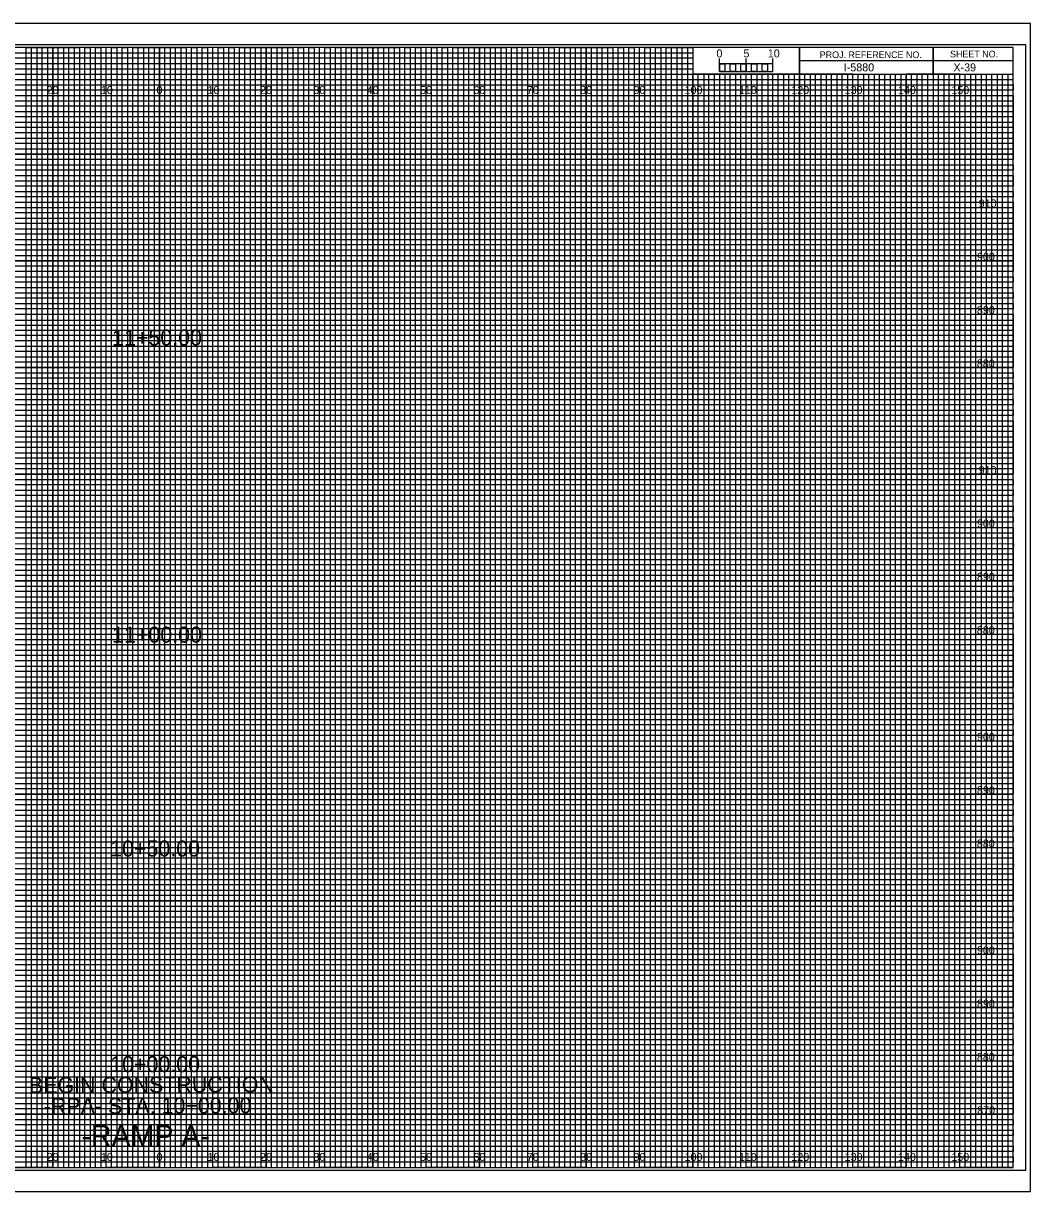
# Model space of a CAD drawing. Extents: x -13 to 323, y -4 to 214.
# Drawn here: x 134.5 to 323.3, y -4.5 to 214.5 of the extents above; entities that cross this region are included whole.
import ezdxf

# ---------------------------------------------------------------- set-up
doc = ezdxf.new("R2010")
doc.units = 0
for name, color, linetype in [('Prop XS Alignment Label', 7, 'Continuous'), ('Prop XS Bar Scale Labels', 7, 'Continuous'), ('Prop XS Elevation Labels', 7, 'Continuous'), ('Prop XS Offset Labels', 7, 'Continuous'), ('Prop XS Project Number', 7, 'Continuous'), ('Prop XS SE Text', 7, 'Continuous'), ('Prop XS Sheet Number', 7, 'Continuous'), ('Prop XS Station Labels', 7, 'Continuous'), ('Sheet Cross Section CELL', 7, 'Continuous'), ('Sheet Cross Section Grid Major CELL', 7, 'Continuous'), ('Sheet Cross Section Grid Middle CELL', 7, 'Continuous'), ('Sheet Cross Section Grid Minor 1 CELL', 7, 'Continuous'), ('Sheet Cross Section Grid Minor 2 CELL', 7, 'Continuous'), ('Sheet Cross Section Scale CELL', 7, 'Continuous'), ('Sheet Cutting Line CELL', 7, 'Continuous'), ('Sheet DOT Grid CELL', 7, 'Continuous'), ('Sheet Plot Border Inside CELL', 7, 'Continuous'), ('Sheet Plot Border Outside CELL', 7, 'Continuous')]:
    doc.layers.add(name, color=color, linetype=linetype)

msp = doc.modelspace()

# ---------------------------------------------------------------- linework, layer by layer
at = {"layer": 'Sheet Cross Section CELL'}
for p, q in [((305, 210), (305, 205)), ((305, 205), (305, 210)), ((280, 207.5), (280, 205)), ((320, 207.49), (280, 207.49)), ((280, 205), (320, 205))]:
    msp.add_line(p, q, dxfattribs=at)
for points in [[(320, 210), (0, 210), (0, 0), (320, 0)], [(280, 210), (260, 210), (260, 205.03), (280, 205.03)], [(320, 210), (280, 210), (280, 205), (320, 205)]]:
    msp.add_lwpolyline(points, close=True, dxfattribs=at)
at = {"layer": 'Sheet Cross Section Grid Major CELL'}
for p, q in [((150, 210), (140, 210)), ((140, 210), (140, 0)), ((150, 0), (150, 210)), ((170, 210), (160, 210)), ((160, 210), (160, 0)), ((170, 0), (170, 210)), ((190, 210), (180, 210)), ((180, 210), (180, 0)), ((190, 0), (190, 210)), ((210, 210), (200, 210)), ((200, 210), (200, 0)), ((210, 0), (210, 210)), ((230, 210), (220, 210)), ((220, 210), (220, 0)), ((230, 0), (230, 210)), ((250, 210), (240, 210)), ((240, 210), (240, 0)), ((250, 0), (250, 210)), ((260, 210), (260, 0)), ((270, 0), (270, 205)), ((290, 205), (280, 205)), ((280, 205), (280, 0)), ((290, 0), (290, 205)), ((310, 205), (300, 205)), ((300, 205), (300, 0)), ((310, 0), (310, 205)), ((140, 0), (130, 0)), ((160, 0), (150, 0)), ((180, 0), (170, 0)), ((200, 0), (190, 0)), ((220, 0), (210, 0)), ((240, 0), (230, 0)), ((260, 0), (250, 0)), ((280, 0), (270, 0)), ((300, 0), (290, 0)), ((320, 0), (310, 0)), ((320, 0), (320, 0))]:
    msp.add_line(p, q, dxfattribs=at)
for points in [[(0, 200), (320, 200), (320, 190), (0, 190)], [(0, 180), (320, 180), (320, 170), (0, 170)], [(0, 160), (320, 160), (320, 150), (0, 150)], [(0, 140), (320, 140), (320, 130), (0, 130)], [(0, 120), (320, 120), (320, 110), (0, 110)], [(0, 100), (320, 100), (320, 90), (0, 90)], [(0, 80), (320, 80), (320, 70), (0, 70)], [(0, 60), (320, 60), (320, 50), (0, 50)], [(0, 40), (320, 40), (320, 30), (0, 30)], [(0, 20), (320, 20), (320, 10), (0, 10)]]:
    msp.add_lwpolyline(points, dxfattribs=at)
at = {"layer": 'Sheet Cross Section Grid Middle CELL'}
for points in [[(125, 0), (135, 0), (135, 210), (145, 210), (145, 0), (155, 0), (155, 210), (165, 210), (165, 0), (175, 0), (175, 210), (185, 210), (185, 0), (195, 0), (195, 210), (205, 210), (205, 0), (215, 0), (215, 210), (225, 210), (225, 0), (235, 0), (235, 210), (245, 210), (245, 0), (255, 0), (255, 210), (259.93, 210), (260, 210), (260, 205), (264.99, 205), (264.99, 0), (275, 0), (275, 205), (285, 205), (285, 0), (295, 0), (295, 205), (305, 205), (305, 0), (315, 0), (315, 205)], [(0, 205), (275, 205)], [(0, 185), (320, 185), (320, 195), (0, 195)], [(0, 165), (320, 165), (320, 175), (0, 175)], [(0, 145), (320, 145), (320, 155), (0, 155)], [(0, 125), (320, 125), (320, 135), (0, 135)], [(0, 105), (320, 105), (320, 115), (0, 115)], [(0, 85), (320, 85), (320, 95), (0, 95)], [(0, 65), (320, 65), (320, 75), (0, 75)], [(0, 45), (320, 45), (320, 55), (0, 55)], [(0, 25), (320, 25), (320, 35), (0, 35)], [(0, 5), (320, 5), (320, 15), (0, 15)]]:
    msp.add_lwpolyline(points, dxfattribs=at)
at = {"layer": 'Sheet Cross Section Grid Minor 1 CELL'}
for p, q in [((0, 209), (260, 209)), ((260, 209), (260, 207.98)), ((260, 207.98), (0, 207.98)), ((0, 207), (260, 207)), ((260, 205.89), (0, 205.89)), ((260, 207), (260, 205.89)), ((0, 204), (320, 204))]:
    msp.add_line(p, q, dxfattribs=at)
for points in [[(0, 203), (270, 203), (320, 203), (320, 202), (0, 202)], [(0, 201), (320, 201), (320, 199), (0, 199)], [(0, 198), (320, 198), (320, 197), (0, 196.98)], [(0, 196), (320, 196), (320, 194), (0, 194)], [(0, 193), (320, 193), (320, 192), (0, 192)], [(0, 191), (320, 191), (320, 189), (0, 189)], [(0, 188), (320, 188), (320, 187), (0, 187)], [(0, 186), (320, 186), (320, 184), (0, 184)], [(0, 183), (320, 183), (320, 182), (0, 182)], [(0, 181), (320, 181), (320, 179), (0, 179)], [(0, 178), (320, 178), (320, 177), (0, 177)], [(0, 176), (320, 176), (320, 173.95), (320, 173), (320, 172), (0, 172)], [(0, 174), (320, 174), (320, 173), (0, 173)], [(0, 171), (320, 171), (320, 169), (0, 169.03)], [(0, 169.03), (320, 169), (320, 168), (0, 168)], [(0, 167), (320, 167), (320, 166), (0, 166)], [(0, 164), (320, 164), (320, 163), (0, 163)], [(0, 162), (320, 162), (320, 161), (0, 161)], [(-0.07, 158.89), (320, 158.89), (320, 157.88), (-0.07, 157.88)], [(0, 157), (320, 157), (320, 156), (0, 156)], [(0, 154), (320, 154), (320, 153), (0, 153)], [(0, 152), (320, 152), (320, 151), (0, 151)], [(0, 149), (320, 149), (320, 148), (0, 148)], [(0, 147), (320, 147), (320, 146), (0, 146)], [(0, 144), (320, 144), (320, 143), (0, 143)], [(0, 142), (320, 142), (320, 141), (0, 141)], [(0, 139), (320, 139), (319.99, 137.98), (0, 138)], [(0, 137), (320, 137), (320, 136), (0, 136)], [(0, 134), (320, 134), (320, 133), (0, 133)], [(0, 132), (320, 132), (320, 131), (0, 131)], [(0, 129), (320, 129), (320, 128), (0, 128)], [(0, 127), (320, 127), (320, 126), (0, 126)], [(0, 124), (320, 124), (320, 123), (0, 123)], [(0, 122), (320, 122), (320, 121), (0, 121)], [(0, 119), (320, 119), (320, 118), (0, 118)], [(0, 116.99), (320.07, 116.91), (320, 116), (0, 116)], [(0, 114), (320, 114), (320, 113), (0, 113)], [(0, 112), (320, 112), (320, 111), (0, 111)], [(0, 109), (320, 109), (320, 108), (0, 108)], [(0, 107), (320, 107), (320, 106), (0, 106)], [(0, 104), (320, 104), (320, 103), (0, 103)], [(0, 102), (320, 102), (320, 101), (0, 101)], [(0, 99), (320, 99), (320, 98), (0, 98)], [(0, 97), (320, 97), (320, 96), (0, 96)], [(0, 94), (320, 94), (320, 93), (0, 93)], [(0, 92), (320, 92), (320, 91), (0, 91)], [(0, 89), (320, 89), (320, 88), (0, 88)], [(0, 87), (320, 87), (320, 86), (0, 86)], [(0, 84), (320, 84), (320, 83), (0, 83)], [(0, 82), (320, 82), (320, 81), (0, 81)], [(0, 79), (320, 79), (319.99, 77.98), (0, 78)], [(0, 77), (320, 77), (320, 76), (0, 76)], [(0, 74), (320, 74), (320, 73), (0, 73)], [(0, 72), (320, 72), (320, 71), (0, 71)], [(0, 69), (320, 69), (320, 68), (0, 68)], [(0, 67), (320, 67), (320, 66), (0, 66)], [(0, 64), (320, 64), (320, 63), (0, 63)], [(0, 62), (320, 62), (320, 61), (0, 61)], [(0, 59), (320, 59), (320, 58), (0, 58)], [(0, 56.99), (320.07, 56.91), (320, 56), (0, 56)], [(0, 54), (320, 54), (320, 53), (0, 53)], [(0, 52), (320, 52), (320, 51), (0, 51)], [(0, 49), (320, 49), (320, 48), (0, 48)], [(0, 47), (320, 47), (320, 46), (0, 46)], [(0, 44), (320, 44), (320, 43), (0, 43)], [(0, 42), (320, 42), (320, 41), (0, 41)], [(0, 39), (320, 39), (320, 38), (0, 38)], [(0, 37), (320, 37), (320, 36), (0, 36)], [(0, 34), (320, 34), (320, 33), (0, 33)], [(0, 32), (320, 32), (320, 31), (0, 31)], [(0, 29), (320, 29), (320, 28), (0, 28)], [(0, 27), (320, 27), (320, 26), (0, 26)], [(0, 24), (320, 24), (320, 23), (0, 23)], [(0, 22), (320, 22), (320, 21), (0, 21)], [(0, 19), (320, 19), (320, 18), (0, 18)], [(0, 17), (320, 17), (320, 16), (0, 16)], [(0, 14), (320, 14), (320, 13), (0, 13)], [(0, 12), (320, 12), (320, 11), (0, 11)], [(0, 9), (320, 9), (320, 8), (0, 8)], [(0, 7), (320, 7), (320, 6), (0, 6)], [(0, 4), (320, 4), (320, 3), (0, 3)], [(0, 2), (320, 2), (320, 1), (0, 1)]]:
    msp.add_lwpolyline(points, dxfattribs=at)
at = {"layer": 'Sheet Cross Section Grid Minor 2 CELL'}
for p, q in [((267, 205), (266.01, 205)), ((266.01, 205), (266.01, 0)), ((267, 0), (267, 205)), ((269, 205), (268, 205)), ((268, 205), (268, 0)), ((269, 0), (269, 205)), ((266.01, 0), (265, 0)), ((268, 0), (267, 0))]:
    msp.add_line(p, q, dxfattribs=at)
for points in [[(135, 0), (136, 0), (136, 210), (137, 210), (137, 0)], [(137, 0), (138, 0), (138, 210), (139, 210), (139, 0)], [(140, 0), (141, 0), (141, 210), (142, 210), (142, 0)], [(142, 0), (143, 0), (143, 210), (144, 210), (144, 0)], [(145, 0), (146, 0), (146, 210), (147, 210), (147, 0)], [(147, 0), (148, 0), (148, 210), (149, 210), (149, 0)], [(150, 0), (151, 0), (151, 210), (152, 210), (152, 0)], [(152, 0), (153, 0), (153, 210), (154, 210), (154, 0)], [(155, 0), (156, 0), (156, 210), (157, 210), (157, 0)], [(157, 0), (158, 0), (158, 210), (159, 210), (159, 0)], [(160, 0), (161, 0), (161, 210), (162, 210), (162, 0)], [(162, 0), (163, 0), (163, 210), (164, 210), (164, 0)], [(165, 0), (166, 0), (166, 210), (167, 210), (167, 0)], [(167, 0), (168, 0), (168, 210), (169, 210), (169, 0)], [(170, 0), (171, 0), (171, 210), (172, 210), (172, 0)], [(172, 0), (173, 0), (173, 210), (174, 210), (174, 0)], [(175, 0), (176, 0), (176, 210), (177, 210), (177, 0)], [(177, 0), (178, 0), (178, 210), (179, 210), (179, 0)], [(180, 0), (181, 0), (181, 210), (182, 210), (182, 0)], [(182, 0), (183, 0), (183, 210), (184, 210), (184, 0)], [(185, 0), (186, 0), (186, 210), (187, 210), (187, 0)], [(187, 0), (188, 0), (188, 210), (189, 210), (189, 0)], [(190, 0), (191, 0), (191, 210), (192, 210), (192, 0)], [(192, 0), (193, 0), (193, 210), (194, 210), (194, 0)], [(195, 0), (196, 0), (196, 210), (197, 210), (197, 0)], [(197, 0), (198, 0), (198, 210), (199, 210), (199, 0)], [(200, 0), (201, 0), (201, 210), (202, 210), (202, 0)], [(202, 0), (203, 0), (203, 210), (204, 210), (204, 0)], [(205, 0), (206, 0), (206, 210), (207, 210), (207, 0)], [(207, 0), (208, 0), (208, 210), (209, 210), (209, 0)], [(210, 0), (211, 0), (211, 210), (212, 210), (212, 0)], [(212, 0), (213, 0), (213, 210), (214, 210), (214, 0)], [(215, 0), (216, 0), (216, 210), (217, 210), (217, 0)], [(217, 0), (218, 0), (218, 210), (219, 210), (219, 0)], [(220, 0), (221, 0), (221, 210), (222, 210), (222, 0)], [(222, 0), (223, 0), (223, 210), (224, 210), (224, 0)], [(225, 0), (226, 0), (226, 210), (227, 210), (227, 0)], [(227, 0), (228, 0), (228, 210), (229, 210), (229, 0)], [(230, 0), (231, 0), (231, 210), (232, 210), (232, 0)], [(232, 0), (233, 0), (233, 210), (234, 210), (234, 0)], [(235, 0), (236, 0), (236, 210), (237, 210), (237, 0)], [(237, 0), (238, 0), (238, 210), (239, 210), (239, 0)], [(240, 0), (241, 0), (241, 210), (242, 210), (242, 0)], [(242, 0), (243, 0), (243, 210), (244, 210), (244, 0)], [(245, 0), (246, 0), (246, 210), (247, 210), (247, 0)], [(247, 0), (248, 0), (248, 210), (249, 210), (249, 0)], [(250, 0), (251, 0), (251, 210), (252, 210), (252, 0)], [(252, 0), (253, 0), (253, 210), (254, 210), (254, 0)], [(255, 0), (256, 0), (256, 210), (257, 210), (257, 0)], [(257, 0), (258, 0), (258, 210), (259, 210), (259, 0)], [(260, 0), (261, 0), (261, 205), (262.02, 205), (262.02, 0)], [(262, 0), (263, 0), (263, 205), (263.99, 205), (263.99, 0)], [(270, 0), (270.98, 0), (270.98, 205), (272, 205), (272, 0)], [(272, 0), (273, 0), (273, 205), (274.05, 205), (274.05, 0)], [(275, 0), (276, 0), (276, 205), (277, 205), (277, 0)], [(277, 0), (278, 0), (278, 205), (279, 205), (279, 0)], [(280, 0), (281, 0), (281, 205), (282, 205), (282, 0)], [(282, 0), (283, 0), (283, 205), (284, 205), (284, 0)], [(285, 0), (286, 0), (286, 205), (287, 205), (287, 0)], [(287, 0), (288, 0), (288, 205), (289, 205), (289, 0)], [(290, 0), (291, 0), (291, 205), (292, 205), (292, 0)], [(292, 0), (293, 0), (293, 205), (294, 205), (294, 0)], [(295, 0), (296, 0), (296, 205), (297, 205), (297, 0)], [(297, 0), (298, 0), (298, 205), (299, 205), (299, 0)], [(300, 0), (301, 0), (301, 205), (302, 205), (302, 0)], [(302, 0), (303, 0), (303, 205), (304, 205), (304, 0)], [(305, 0), (306, 0), (306, 205), (307, 205), (307, 0)], [(307, 0), (308, 0), (308, 205), (309, 205), (309, 0)], [(310, 0), (311, 0), (311, 205), (312, 205), (312, 0)], [(312, 0), (313, 0), (313, 205), (314, 205), (314, 0)], [(315, 0), (316, 0), (316, 205), (317, 205), (317, 0)], [(317, 0), (318, 0), (318, 205), (319, 205), (319, 0)]]:
    msp.add_lwpolyline(points, dxfattribs=at)
at = {"layer": 'Sheet Cross Section Scale CELL'}
for p, q in [((265, 205.49), (265, 207.9)), ((265, 206.9), (265, 207.9)), ((270, 205.49), (270, 207.9)), ((275, 205.49), (275, 207.9)), ((275, 206.9), (275, 207.9))]:
    msp.add_line(p, q, dxfattribs=at)
for points in [[(275, 206.9), (265, 206.9), (265, 205.49), (275, 205.49)], [(265, 206.9), (266, 206.9), (266, 205.49), (265, 205.49)], [(267, 206.9), (268, 206.9), (268, 205.49), (267, 205.49)], [(269, 206.9), (270, 206.9), (270, 205.49), (269, 205.49)], [(271, 206.9), (272, 206.9), (272, 205.49), (271, 205.49)], [(273, 206.9), (274, 206.9), (274, 205.49), (273, 205.49)]]:
    msp.add_lwpolyline(points, close=True, dxfattribs=at)
at = {"layer": 'Sheet Cutting Line CELL'}
for p, q in [((323.3, 214.5), (-13.4, 214.5)), ((-13.4, -4.5), (323.3, -4.5))]:
    msp.add_line(p, q, dxfattribs=at)
at = {"layer": 'Sheet DOT Grid CELL'}
for p, q in [((140, 0), (140, 210)), ((150, 0), (150, 210)), ((160, 0), (160, 210)), ((170, 0), (170, 210)), ((180, 0), (180, 210)), ((190, 0), (190, 210)), ((200, 0), (200, 210)), ((210, 0), (210, 210)), ((220, 0), (220, 210)), ((230, 0), (230, 210)), ((240, 0), (240, 210)), ((250, 0), (250, 210)), ((260, 0), (260, 204.69)), ((270, 0), (270, 204.69)), ((280, 0), (280, 204.69)), ((290, 0), (290, 204.69)), ((300, 0), (300, 204.69)), ((310, 0), (310, 204.69)), ((0, 200), (320, 200)), ((0, 190), (320, 190)), ((0, 180), (320, 180)), ((0, 170), (320, 170)), ((0, 160), (320, 160)), ((0, 150), (320, 150)), ((0, 140), (320, 140)), ((0, 130), (320, 130)), ((0, 120), (320, 120)), ((0, 110), (320, 110)), ((0, 100), (320, 100)), ((0, 90), (320, 90)), ((0, 80), (320, 80)), ((0, 70), (320, 70)), ((0, 60), (320, 60)), ((0, 50), (320, 50)), ((0, 40), (320, 40)), ((0, 30), (320, 30)), ((0, 20), (320, 20)), ((0, 10), (320, 10))]:
    msp.add_line(p, q, dxfattribs=at)
at = {"layer": 'Sheet Plot Border Inside CELL'}
msp.add_lwpolyline([(-10.8, -0.5), (322.4, -0.5), (322.4, 210.5), (-10.8, 210.5)], close=True, dxfattribs=at)
at = {"layer": 'Sheet Plot Border Outside CELL'}
msp.add_lwpolyline([(-13.4, -4.5), (323.3, -4.5), (323.3, 214.5), (-13.4, 214.5)], close=True, dxfattribs=at)

# ---------------------------------------------------------------- texts
at = {"layer": 'Prop XS Alignment Label'}
msp.add_text('-RAMP A-', height=4, dxfattribs=at).set_placement((145.39, 4))
at = {"layer": 'Prop XS Bar Scale Labels'}
for s, p in [('5', (269.47, 208.12)), ('10', (274.04, 208.12))]:
    msp.add_text(s, height=1.5, dxfattribs=at).set_placement(p)
at = {"layer": 'Prop XS Elevation Labels'}
for s, p in [('910', (313.57, 180)), ('900', (313.24, 170)), ('890', (313.24, 160)), ('880', (313.22, 150)), ('910', (313.57, 130)), ('900', (313.24, 120)), ('890', (313.24, 110)), ('880', (313.22, 100)), ('900', (313.24, 80)), ('890', (313.24, 70)), ('880', (313.22, 60)), ('900', (313.24, 40)), ('890', (313.24, 30)), ('880', (313.22, 20)), ('870', (313.28, 10))]:
    msp.add_text(s, height=1.5, dxfattribs=at).set_placement(p)
at = {"layer": 'Prop XS Offset Labels'}
for s, p in [('20', (138.86, 201.25)), ('10', (149.04, 201.25)), ('0', (159.45, 201.25)), ('0', (159.45, 201.25)), ('10', (169.04, 201.25)), ('20', (178.86, 201.25)), ('30', (188.86, 201.25)), ('40', (198.86, 201.25)), ('50', (208.86, 201.25)), ('60', (218.86, 201.25)), ('70', (228.86, 201.25)), ('80', (238.86, 201.25)), ('90', (248.86, 201.25)), ('100', (258.44, 201.25)), ('110', (268.62, 201.25)), ('120', (278.44, 201.25)), ('130', (288.44, 201.25)), ('140', (298.44, 201.25)), ('150', (308.44, 201.25)), ('20', (138.86, 1.25)), ('10', (149.04, 1.25)), ('0', (159.45, 1.25)), ('0', (159.45, 1.25)), ('10', (169.04, 1.25)), ('20', (178.86, 1.25)), ('30', (188.86, 1.25)), ('40', (198.86, 1.25)), ('50', (208.86, 1.25)), ('60', (218.86, 1.25)), ('70', (228.86, 1.25)), ('80', (238.86, 1.25)), ('90', (248.86, 1.25)), ('100', (258.44, 1.25)), ('110', (268.62, 1.25)), ('120', (278.44, 1.25)), ('130', (288.44, 1.25)), ('140', (298.44, 1.25)), ('150', (308.44, 1.25))]:
    msp.add_text(s, height=1.5, dxfattribs=at).set_placement(p)
at = {"layer": 'Prop XS Project Number'}
msp.add_text('I-5880', height=1.5, dxfattribs=at).set_placement((288.28, 205.5))
at = {"layer": 'Prop XS SE Text'}
for s, p in [('BEGIN CONSTRUCTION', (135.55, 13.95)), ('-RPA- STA. 10+00.00', (138.34, 10.03))]:
    msp.add_text(s, height=3, rotation=0.2317, dxfattribs=at).set_placement(p)
at = {"layer": 'Prop XS Sheet Number'}
msp.add_text('X-39', height=1.5, dxfattribs=at).set_placement((308.83, 205.5))
at = {"layer": 'Prop XS Station Labels'}
for s, p in [('11+50.00', (151.13, 154.1)), ('11+00.00', (151.13, 98.41)), ('10+50.00', (150.77, 58.33)), ('10+00.00', (150.77, 17.9))]:
    msp.add_text(s, height=3, dxfattribs=at).set_placement(p)
at = {"layer": 'Sheet Cross Section CELL'}
for s, p in [('PROJ. REFERENCE NO.', (283.77, 207.99)), ('SHEET NO.', (308.19, 208.12))]:
    msp.add_text(s, height=1.25, dxfattribs=at).set_placement(p)
at = {"layer": 'Sheet Cross Section Scale CELL'}
msp.add_text('0', height=1.5, dxfattribs=at).set_placement((264.41, 208.12))

doc.saveas('drawing.dxf')
